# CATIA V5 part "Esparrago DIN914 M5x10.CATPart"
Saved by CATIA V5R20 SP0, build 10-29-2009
Part number: Esparrago DIN914 M5x10
Revision: ANY
Definition: UNKNOWN
Nomenclature: Esparrago DIN914 M5x10
Source: Unknown
Bounding box of the stored display mesh (mm): x -2.5 to 2.5, y -2.5 to 2.5, z 0 to 9
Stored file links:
  C:\Users\Utente\Desktop\IO LAVORO\3D X SITO CF\X SITO\3D files UM\UM043642 PRODUCT\Esparrago DIN914 M5x10.CATPart
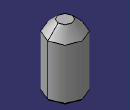
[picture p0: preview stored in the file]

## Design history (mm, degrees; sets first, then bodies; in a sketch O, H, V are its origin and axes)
Body1 "Cortar-Extruir2" (main body)
  Solid1: solid without history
